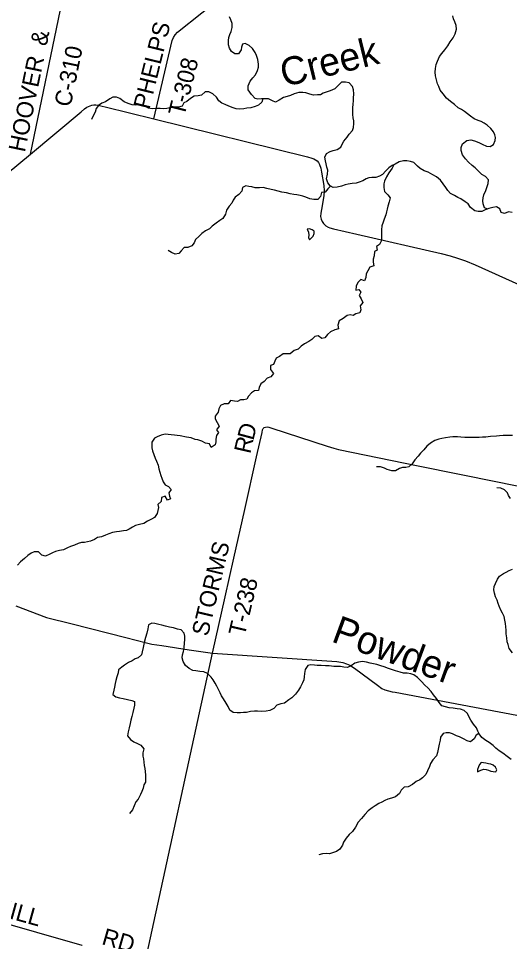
# Model space of a CAD drawing. Extents: x 0 to 34, y 0 to 22.
# Drawn here: x 4.289 to 5.122, y 17.405 to 18.969 of the extents above; entities that cross this region are included whole.
import ezdxf

# ---------------------------------------------------------------- set-up
doc = ezdxf.new("R2010")
doc.units = 0
for name, color, linetype in [('GM_X_County_Road', 7, 'Continuous'), ('GM_X_County_Road_Text', 7, 'Continuous'), ('GM_X_Minor_Lake', 7, 'Continuous'), ('GM_X_Minor_River', 7, 'Continuous'), ('GM_X_Minor_River_Text', 7, 'Continuous'), ('GM_X_State_Route', 7, 'Continuous'), ('GM_X_Township_Road', 7, 'Continuous'), ('GM_X_Township_Road_Text', 7, 'Continuous')]:
    doc.layers.add(name, color=color, linetype=linetype)

msp = doc.modelspace()

# ---------------------------------------------------------------- linework, layer by layer
at = {"layer": 'GM_X_County_Road'}
for points in [[(4.3094, 18.7397), (4.3635, 18.9982), (4.38, 19.0762), (4.4106, 19.2242), (4.44, 19.3619), (4.4954, 19.6213), (4.496, 19.6278)], [(4.2845, 17.9738), (4.3365, 17.9544), (4.3804, 17.9434), (4.4713, 17.9204), (4.5061, 17.9115), (4.5154, 17.9092), (4.5321, 17.9065), (4.5787, 17.8994), (4.6179, 17.894), (4.8287, 17.8794), (4.8392, 17.8777), (4.8453, 17.8759), (4.8506, 17.8734), (4.8585, 17.8684), (4.8976, 17.8393), (4.9051, 17.8341), (4.9104, 17.8318), (4.9166, 17.8299), (4.9228, 17.8284), (4.9275, 17.8274), (5.1759, 17.7808)], [(4.5014, 17.3574), (4.5033, 17.3673), (4.6179, 17.894)]]:
    msp.add_lwpolyline(points, dxfattribs=at)
at = {"layer": 'GM_X_Minor_Lake'}
for points in [[(4.7843, 18.5959), (4.7854, 18.5968), (4.7886, 18.6006), (4.7904, 18.6051), (4.7906, 18.6091), (4.7868, 18.6114), (4.7825, 18.6127), (4.7785, 18.6126)], [(4.7785, 18.6126), (4.7809, 18.6074), (4.7816, 18.6023), (4.7809, 18.5981), (4.7822, 18.5942), (4.7843, 18.5959)], [(5.0986, 17.6992), (5.0978, 17.7007), (5.0939, 17.7042), (5.0901, 17.7059), (5.0857, 17.7063), (5.0814, 17.7073), (5.0774, 17.7081), (5.0733, 17.7086), (5.0704, 17.7053), (5.0687, 17.7009), (5.0675, 17.6966), (5.0673, 17.6926)], [(5.0673, 17.6926), (5.073, 17.6956), (5.0781, 17.6972), (5.0821, 17.6968), (5.0859, 17.6953), (5.0896, 17.6936), (5.094, 17.6932), (5.0985, 17.6929), (5.1002, 17.6963), (5.0986, 17.6992)]]:
    msp.add_lwpolyline(points, dxfattribs=at)
at = {"layer": 'GM_X_Minor_River'}
for points in [[(4.8127, 18.8449), (4.8059, 18.8426), (4.8012, 18.8402), (4.7963, 18.8402), (4.7895, 18.8395), (4.783, 18.8413), (4.7762, 18.8434), (4.7711, 18.8442), (4.7642, 18.8437), (4.7566, 18.8416), (4.7503, 18.839), (4.7445, 18.8371), (4.7382, 18.8353), (4.7312, 18.8308), (4.7249, 18.8274), (4.72, 18.8299), (4.7131, 18.833), (4.7068, 18.8332), (4.701, 18.8331), (4.6951, 18.8327), (4.6902, 18.8335), (4.684, 18.8408), (4.6786, 18.8484), (4.6786, 18.8554), (4.6819, 18.863), (4.6864, 18.8688), (4.6908, 18.8737), (4.6946, 18.8813), (4.6962, 18.8866), (4.6958, 18.8919), (4.6947, 18.8999), (4.6925, 18.9065), (4.6903, 18.9116), (4.686, 18.9185), (4.6803, 18.9238), (4.6737, 18.9271), (4.6688, 18.926), (4.6671, 18.9207), (4.6667, 18.916), (4.6623, 18.9097), (4.6559, 18.9092), (4.6504, 18.9134), (4.6467, 18.9189), (4.645, 18.9246), (4.645, 18.9319), (4.6458, 18.9372), (4.6475, 18.9423), (4.6495, 18.9472), (4.6514, 18.954), (4.6514, 18.9606), (4.6494, 18.9671), (4.6468, 18.972)], [(5.0845, 18.6464), (5.0792, 18.6486), (5.0766, 18.6554), (5.0761, 18.6604), (5.0766, 18.6653), (5.0782, 18.6706), (5.0811, 18.6781), (5.083, 18.6831), (5.0853, 18.6897), (5.0859, 18.6961), (5.081, 18.7015), (5.0744, 18.7051), (5.0697, 18.7103), (5.0633, 18.716), (5.0583, 18.72), (5.0522, 18.7259), (5.0468, 18.7317), (5.0421, 18.7381), (5.0397, 18.7454), (5.0393, 18.7505), (5.042, 18.7571), (5.0492, 18.7627), (5.0557, 18.7636), (5.0623, 18.7619), (5.0693, 18.759), (5.0753, 18.7561), (5.0823, 18.7532), (5.0889, 18.7526), (5.0946, 18.7558), (5.0974, 18.7626), (5.0975, 18.7674), (5.0965, 18.7723), (5.0943, 18.7772), (5.09, 18.7828), (5.0838, 18.7883), (5.0785, 18.7918), (5.0734, 18.7948), (5.0681, 18.7966), (5.0616, 18.7995), (5.0552, 18.8039), (5.0501, 18.8077), (5.045, 18.8119), (5.0399, 18.8151), (5.0344, 18.8182), (5.0281, 18.8236), (5.0217, 18.8289), (5.0145, 18.8343), (5.0091, 18.8415), (5.0042, 18.848), (5.0016, 18.8541), (4.9995, 18.8588), (4.9979, 18.8653), (4.9962, 18.8719), (4.9953, 18.8786), (4.9961, 18.8846), (4.9974, 18.8913), (4.9992, 18.8971), (5.0028, 18.9049), (5.007, 18.91), (5.0121, 18.9164), (5.0169, 18.9232), (5.0211, 18.93), (5.0262, 18.9368), (5.0295, 18.9436), (5.0314, 18.9514), (5.0313, 18.9573), (5.029, 18.9637), (5.0268, 18.969), (5.0253, 18.9738)], [(5.126, 18.6403), (5.1198, 18.6415), (5.1132, 18.6387), (5.1073, 18.6408), (5.1053, 18.6467), (5.0994, 18.6503), (5.0932, 18.6492), (5.0867, 18.6472), (5.0805, 18.645), (5.0744, 18.6423), (5.0682, 18.6422), (5.0625, 18.6436), (5.0554, 18.6491), (5.0516, 18.6554), (5.0466, 18.6588), (5.0388, 18.664), (5.0338, 18.6659), (5.0283, 18.6694), (5.0215, 18.673), (5.0168, 18.678), (5.0134, 18.6827), (5.0093, 18.6894), (5.0046, 18.6951), (4.998, 18.7009), (4.9915, 18.7043), (4.9839, 18.7089), (4.9769, 18.7114), (4.9702, 18.7153), (4.9653, 18.7193), (4.9591, 18.7252), (4.9536, 18.7271), (4.9476, 18.7281), (4.9419, 18.7282), (4.9345, 18.7267), (4.9277, 18.7227), (4.9228, 18.7201), (4.9169, 18.716), (4.9119, 18.7113), (4.906, 18.7047), (4.9013, 18.7022), (4.895, 18.6998), (4.8884, 18.6999), (4.8833, 18.6993), (4.8784, 18.6976), (4.8731, 18.6941), (4.8668, 18.692), (4.8615, 18.6905), (4.8549, 18.6898), (4.8483, 18.6885), (4.8432, 18.6873), (4.8367, 18.685), (4.8294, 18.6835), (4.8226, 18.683), (4.8177, 18.6855), (4.8135, 18.691), (4.8115, 18.6979), (4.8132, 18.7057), (4.8133, 18.7121), (4.8118, 18.7174), (4.8107, 18.7229), (4.8094, 18.7282), (4.8083, 18.7345), (4.8112, 18.7407), (4.8176, 18.7439), (4.8227, 18.7454), (4.8294, 18.7471), (4.8358, 18.7512), (4.8377, 18.7563), (4.8406, 18.7614), (4.8465, 18.7684), (4.8497, 18.7733), (4.8551, 18.7793), (4.857, 18.7846), (4.8576, 18.7913), (4.8574, 18.796), (4.8563, 18.8011), (4.8562, 18.8066), (4.8558, 18.8125), (4.8557, 18.8178), (4.8563, 18.8243), (4.8569, 18.8296), (4.8571, 18.8345), (4.8575, 18.8417), (4.8568, 18.8486), (4.8553, 18.8539), (4.8497, 18.8602), (4.8436, 18.8617), (4.837, 18.8612), (4.8313, 18.8559), (4.8252, 18.8499), (4.8177, 18.8465), (4.8127, 18.8449)], [(4.7036, 18.8331), (4.7017, 18.8274), (4.6962, 18.8227), (4.6901, 18.8202), (4.6829, 18.818), (4.6763, 18.8173), (4.6712, 18.8164), (4.6646, 18.8158), (4.658, 18.8165), (4.6529, 18.8178), (4.6459, 18.8207), (4.6393, 18.8238), (4.634, 18.8257), (4.6288, 18.8297), (4.6246, 18.8358), (4.6186, 18.8417), (4.612, 18.8448), (4.6054, 18.8452), (4.5995, 18.8392), (4.594, 18.8385), (4.5868, 18.838), (4.5808, 18.8338), (4.5743, 18.8286), (4.5696, 18.8267), (4.5667, 18.8205), (4.5607, 18.8192), (4.5531, 18.8192), (4.5465, 18.8181), (4.5408, 18.8168), (4.5342, 18.8163), (4.5291, 18.8167), (4.5227, 18.817), (4.516, 18.8162), (4.5096, 18.8176), (4.5034, 18.8209), (4.4985, 18.8222), (4.4919, 18.8228), (4.4868, 18.8227), (4.4819, 18.8233), (4.4751, 18.8252), (4.4685, 18.8279), (4.461, 18.834), (4.4555, 18.8362), (4.4493, 18.8362), (4.4443, 18.8334), (4.4365, 18.8279), (4.4303, 18.8261), (4.4246, 18.8218), (4.421, 18.8167), (4.4192, 18.8108), (4.4162, 18.8057), (4.4127, 18.7983)], [(4.9255, 18.7216), (4.9227, 18.7158), (4.9168, 18.708), (4.9132, 18.701), (4.9094, 18.6938), (4.9086, 18.6891), (4.9082, 18.6827), (4.9096, 18.6762), (4.9155, 18.6707), (4.9194, 18.6655), (4.9175, 18.6585), (4.9154, 18.6515), (4.914, 18.6464), (4.9132, 18.6415), (4.9121, 18.6364), (4.9092, 18.6294), (4.9076, 18.6244), (4.9051, 18.6178), (4.9044, 18.6114), (4.9045, 18.6042), (4.9043, 18.5994), (4.9048, 18.5932), (4.9012, 18.5864), (4.8959, 18.5832), (4.8972, 18.5767), (4.8924, 18.5747), (4.892, 18.5669), (4.8906, 18.5614), (4.8906, 18.5565), (4.8913, 18.55), (4.8849, 18.5478), (4.8813, 18.5417), (4.8788, 18.5366), (4.878, 18.5302), (4.8757, 18.5247), (4.8693, 18.5272), (4.8645, 18.5221), (4.8618, 18.5157), (4.861, 18.5089), (4.8663, 18.5102), (4.8695, 18.5054), (4.8668, 18.5001), (4.87, 18.4942), (4.8728, 18.4881), (4.8681, 18.4823), (4.8694, 18.4758), (4.868, 18.4707), (4.8612, 18.4687), (4.8563, 18.4662), (4.8512, 18.467), (4.8462, 18.4661), (4.8398, 18.461), (4.8328, 18.4571), (4.8305, 18.4495), (4.8319, 18.4436), (4.8253, 18.4418), (4.8179, 18.4381), (4.813, 18.4339), (4.8084, 18.4283), (4.8033, 18.4271), (4.7971, 18.4315), (4.7914, 18.4303), (4.7867, 18.4254), (4.7813, 18.4218), (4.7739, 18.4182), (4.7681, 18.4143), (4.7631, 18.4092), (4.7565, 18.4066), (4.7495, 18.4008), (4.7434, 18.4012), (4.7379, 18.401), (4.7319, 18.3965), (4.726, 18.3937), (4.7239, 18.3888), (4.7214, 18.3831), (4.7165, 18.3813), (4.7164, 18.3746), (4.7215, 18.3678), (4.7169, 18.3621), (4.7109, 18.3597), (4.7055, 18.354), (4.6997, 18.3503), (4.697, 18.3438), (4.6962, 18.3391), (4.6894, 18.3384), (4.6844, 18.335), (4.6789, 18.3295), (4.6763, 18.3241), (4.6711, 18.323), (4.6653, 18.323), (4.6602, 18.32), (4.6551, 18.3206), (4.6485, 18.322), (4.6446, 18.3165), (4.6377, 18.3163), (4.6316, 18.3134), (4.6287, 18.3079), (4.6276, 18.302), (4.6224, 18.2956), (4.6226, 18.2907), (4.6261, 18.2846)], [(4.818, 18.6853), (4.8135, 18.6806), (4.8089, 18.6751), (4.803, 18.6746), (4.8011, 18.6676), (4.7966, 18.6627), (4.7899, 18.6628), (4.7831, 18.6637), (4.7764, 18.6664), (4.7714, 18.6682), (4.7664, 18.6695), (4.7611, 18.6707), (4.7562, 18.6709), (4.7495, 18.6723), (4.7435, 18.6737), (4.7356, 18.6752), (4.7292, 18.6768), (4.7233, 18.6782), (4.7173, 18.6795), (4.7103, 18.6811), (4.7041, 18.6827), (4.6976, 18.6821), (4.6905, 18.6822), (4.6848, 18.6841), (4.6795, 18.6849), (4.6744, 18.6855), (4.6689, 18.6827), (4.6677, 18.6766), (4.6626, 18.6712), (4.6563, 18.6667), (4.6531, 18.6617), (4.6506, 18.6564), (4.6462, 18.6514), (4.642, 18.6446), (4.6399, 18.6376), (4.6353, 18.6306), (4.6306, 18.6272), (4.6243, 18.6223), (4.6177, 18.6172), (4.6127, 18.6127), (4.6063, 18.6097), (4.6002, 18.6048), (4.5947, 18.5997), (4.589, 18.5946), (4.5871, 18.589), (4.5831, 18.5839), (4.5765, 18.5815), (4.5699, 18.5813), (4.5647, 18.5758), (4.5611, 18.5709), (4.5549, 18.5702), (4.5488, 18.5729), (4.543, 18.5764)], [(4.6261, 18.2846), (4.6293, 18.2785), (4.6251, 18.2723), (4.6283, 18.2675), (4.6249, 18.2626), (4.6237, 18.2565), (4.6235, 18.2518), (4.6225, 18.2469), (4.616, 18.2422), (4.6129, 18.2486), (4.6061, 18.2498), (4.6, 18.2529), (4.5934, 18.2554), (4.5885, 18.256), (4.5819, 18.2587), (4.574, 18.2599), (4.5634, 18.2622), (4.5583, 18.2626), (4.5534, 18.2634), (4.5478, 18.2638), (4.5427, 18.2643), (4.5377, 18.2647), (4.5311, 18.2634), (4.5245, 18.2606), (4.5198, 18.2582), (4.5152, 18.2515), (4.515, 18.2464), (4.5153, 18.2417), (4.5166, 18.2366), (4.5185, 18.2305), (4.5209, 18.2244), (4.5233, 18.2191), (4.5257, 18.2124), (4.5272, 18.2061), (4.5289, 18.2004), (4.5303, 18.1951), (4.5322, 18.1904), (4.5346, 18.1839), (4.5378, 18.1792), (4.5435, 18.1761), (4.548, 18.1709), (4.5442, 18.1653), (4.5453, 18.1601), (4.5466, 18.1554), (4.5416, 18.1533), (4.5377, 18.1596), (4.5314, 18.1574), (4.5308, 18.1506), (4.5253, 18.1459), (4.5266, 18.1409), (4.5253, 18.1356), (4.5241, 18.1307), (4.5197, 18.1235), (4.5146, 18.1207), (4.5076, 18.1172), (4.5017, 18.1134), (4.4945, 18.1117), (4.4877, 18.1099), (4.4822, 18.1071), (4.4769, 18.1039), (4.4721, 18.1018), (4.467, 18.1013), (4.4604, 18.1002), (4.4553, 18.0995), (4.4483, 18.098), (4.4423, 18.0958), (4.4368, 18.0937), (4.4299, 18.0911), (4.4231, 18.0897), (4.418, 18.0865), (4.4112, 18.0835), (4.4061, 18.0824), (4.401, 18.0815), (4.3959, 18.0813), (4.3906, 18.0798), (4.3843, 18.077), (4.3775, 18.0746), (4.3722, 18.072), (4.3657, 18.069), (4.3586, 18.0677), (4.3519, 18.0658), (4.347, 18.0636), (4.3423, 18.0616), (4.3351, 18.058), (4.3286, 18.0596), (4.323, 18.0653), (4.316, 18.0655), (4.3109, 18.0633), (4.305, 18.0595), (4.2991, 18.0541), (4.2927, 18.0484), (4.2873, 18.0428)], [(5.1264, 18.2624), (5.1213, 18.2624), (5.1162, 18.2624), (5.1106, 18.2627), (5.1043, 18.2619), (5.0992, 18.2616), (5.0894, 18.2609), (5.0815, 18.26), (5.0756, 18.2597), (5.0701, 18.2593), (5.0641, 18.2592), (5.058, 18.2592), (5.0523, 18.2594), (5.0459, 18.2595), (5.0391, 18.2599), (5.0335, 18.2605), (5.0257, 18.2602), (5.0202, 18.2598), (5.013, 18.2589), (5.0066, 18.2576), (5.0017, 18.2562), (4.9949, 18.2539), (4.9878, 18.2494), (4.9816, 18.2447), (4.9764, 18.2383), (4.9709, 18.2325), (4.9664, 18.2276), (4.961, 18.2215), (4.9565, 18.2149), (4.9509, 18.2098), (4.9458, 18.2083), (4.9402, 18.2082), (4.9352, 18.2069), (4.9284, 18.203), (4.922, 18.2026), (4.9144, 18.2053), (4.9095, 18.2071), (4.9031, 18.2096), (4.8963, 18.2094)], [(5.123, 18.156), (5.12, 18.1608), (5.1181, 18.1655), (5.1129, 18.1707), (5.1066, 18.1732), (5.1002, 18.1738)], [(5.0958, 17.9954), (5.0947, 18.0009), (5.0956, 18.0066), (5.0976, 18.0121), (5.1014, 18.0192), (5.1044, 18.0242), (5.1111, 18.029), (5.1158, 18.0313), (5.1207, 18.0337), (5.1264, 18.036)], [(5.1267, 17.8945), (5.1211, 17.9017), (5.1191, 17.9082), (5.1178, 17.913), (5.1171, 17.92), (5.116, 17.9268), (5.1156, 17.9325), (5.1155, 17.9382), (5.1146, 17.9443), (5.1134, 17.9496), (5.1122, 17.9557), (5.1095, 17.9614), (5.1066, 17.9667), (5.1041, 17.9732), (5.1023, 17.9781), (5.1004, 17.9834), (5.0976, 17.9895), (5.0958, 17.9954)], [(4.8723, 17.8795), (4.8654, 17.8788), (4.8596, 17.8769), (4.8533, 17.8722), (4.8471, 17.8696), (4.8406, 17.8702), (4.835, 17.8714), (4.8238, 17.8714), (4.8157, 17.8721), (4.8097, 17.8725), (4.8025, 17.8727), (4.7957, 17.873), (4.7908, 17.8736), (4.7845, 17.8738), (4.7794, 17.8727), (4.7754, 17.8661), (4.7739, 17.8591), (4.7736, 17.8536), (4.7729, 17.8486), (4.7707, 17.8437), (4.7675, 17.8369), (4.7637, 17.8311), (4.7589, 17.8245), (4.7526, 17.8182), (4.7473, 17.8149), (4.7403, 17.809), (4.7341, 17.8079), (4.727, 17.8055), (4.7219, 17.8001), (4.7153, 17.7965), (4.709, 17.7954), (4.7011, 17.7951), (4.6943, 17.7957), (4.689, 17.7957), (4.6822, 17.795), (4.6756, 17.7935), (4.6707, 17.7932), (4.6657, 17.7925), (4.6597, 17.7927), (4.6531, 17.7935), (4.6476, 17.7969), (4.6444, 17.8034), (4.6413, 17.8089), (4.6368, 17.8162), (4.6334, 17.8213), (4.631, 17.8266), (4.628, 17.8321), (4.6252, 17.8377), (4.6228, 17.8428), (4.619, 17.8483), (4.6156, 17.8531), (4.6098, 17.8594), (4.6034, 17.8619), (4.5968, 17.8627), (4.5896, 17.8639), (4.5845, 17.8643), (4.5783, 17.8677), (4.5721, 17.8727), (4.5684, 17.8796), (4.5669, 17.886), (4.5671, 17.8908), (4.569, 17.8966), (4.5702, 17.9034), (4.5708, 17.9108), (4.5714, 17.9167), (4.5711, 17.9228), (4.5702, 17.9275), (4.5651, 17.9331), (4.5587, 17.9346), (4.5517, 17.9366), (4.5449, 17.9379), (4.5383, 17.9395), (4.5321, 17.941), (4.5271, 17.9424), (4.5202, 17.944), (4.5151, 17.9446), (4.5096, 17.9416), (4.5084, 17.9349), (4.5066, 17.9277), (4.5045, 17.9206), (4.503, 17.9143), (4.5018, 17.9088), (4.5006, 17.9035), (4.4987, 17.8961), (4.4975, 17.8908), (4.4918, 17.8858), (4.4869, 17.8841), (4.482, 17.8809), (4.4754, 17.8777), (4.4689, 17.8734), (4.4642, 17.8702), (4.4587, 17.8653), (4.4579, 17.8604), (4.4561, 17.8538), (4.4542, 17.8473), (4.4528, 17.8422), (4.4519, 17.8361), (4.4507, 17.8308), (4.449, 17.8238), (4.454, 17.8196), (4.4603, 17.8181)], [(5.1243, 17.7136), (5.1176, 17.7186), (5.1102, 17.7243), (5.1042, 17.7285), (5.0984, 17.7326), (5.0937, 17.7375), (5.0873, 17.7421), (5.0814, 17.7456), (5.0747, 17.7509), (5.0698, 17.757), (5.0677, 17.7618), (5.0653, 17.7671), (5.0606, 17.7736), (5.0561, 17.7801), (5.0524, 17.7863), (5.0503, 17.7917), (5.0445, 17.7964), (5.0387, 17.7987), (5.0328, 17.7995), (5.0258, 17.8005), (5.0194, 17.8013), (5.013, 17.8029), (5.0069, 17.8046), (5.0024, 17.8102), (4.9976, 17.8168), (4.9929, 17.8231), (4.9888, 17.829), (4.9833, 17.8349), (4.9782, 17.8395), (4.9724, 17.8458), (4.9656, 17.8523), (4.9594, 17.8569), (4.954, 17.8588), (4.9479, 17.86), (4.9417, 17.8601), (4.936, 17.8618), (4.9283, 17.8637), (4.9215, 17.8663), (4.9162, 17.8678), (4.9092, 17.8705), (4.9036, 17.8722), (4.8964, 17.8744), (4.8908, 17.8756), (4.8851, 17.8769), (4.8792, 17.8785), (4.8723, 17.8795)], [(4.4603, 17.8181), (4.4665, 17.8171), (4.474, 17.8155), (4.4812, 17.8134), (4.4861, 17.812), (4.4861, 17.8054), (4.4847, 17.8003), (4.4828, 17.7935), (4.4812, 17.7867), (4.4799, 17.7802), (4.4785, 17.7744), (4.4766, 17.767), (4.4749, 17.7603), (4.4741, 17.7535), (4.4789, 17.7474), (4.4848, 17.7434), (4.4908, 17.7405), (4.4966, 17.7376), (4.5015, 17.7319), (4.5002, 17.7251), (4.4997, 17.7194), (4.5009, 17.7145), (4.5018, 17.7092), (4.5023, 17.7035), (4.5034, 17.6985), (4.5039, 17.6932), (4.5043, 17.6872), (4.5044, 17.6818), (4.5042, 17.6754), (4.5019, 17.6705), (4.5004, 17.6648), (4.4981, 17.6593), (4.4961, 17.654), (4.4921, 17.6465), (4.4881, 17.6416), (4.4853, 17.6348), (4.4822, 17.6283), (4.4772, 17.6219)], [(5.0696, 17.7576), (5.0649, 17.7546), (5.0618, 17.7485), (5.0555, 17.7435), (5.0497, 17.7454), (5.0433, 17.7487), (5.0369, 17.7517), (5.0316, 17.7535), (5.0248, 17.7571), (5.0197, 17.7587), (5.0144, 17.7589), (5.0093, 17.7576), (5.0047, 17.7514), (5.0038, 17.7463), (5.0024, 17.7393), (5.0006, 17.7309), (4.9997, 17.7254), (4.9976, 17.7199), (4.9917, 17.7132), (4.9877, 17.7069), (4.9857, 17.7016), (4.9823, 17.6941), (4.9798, 17.6884), (4.9741, 17.6827), (4.9693, 17.6792), (4.9633, 17.6764), (4.957, 17.6711), (4.9496, 17.6675), (4.943, 17.6665), (4.9379, 17.6614), (4.9352, 17.6561), (4.9285, 17.6504), (4.9215, 17.6482), (4.9151, 17.6463), (4.9102, 17.6441), (4.9051, 17.6415), (4.8999, 17.6391), (4.8939, 17.6349), (4.8887, 17.6317), (4.8819, 17.6263), (4.8764, 17.6206), (4.8709, 17.6133), (4.8652, 17.6076), (4.8602, 17.5991), (4.8554, 17.5914), (4.8495, 17.5865), (4.8446, 17.5804), (4.8402, 17.5735), (4.8383, 17.5685), (4.8341, 17.5617), (4.8282, 17.5578), (4.8212, 17.5552), (4.8161, 17.5537), (4.8108, 17.5545), (4.8046, 17.5536), (4.7983, 17.5521)]]:
    msp.add_lwpolyline(points, dxfattribs=at)
at = {"layer": 'GM_X_State_Route'}
msp.add_lwpolyline([(4.1938, 18.6441), (4.3094, 18.7397), (4.3952, 18.8112), (4.4012, 18.8161), (4.4051, 18.8188), (4.4078, 18.8203), (4.4106, 18.8214), (4.4136, 18.8223), (4.417, 18.8228), (4.4204, 18.8228), (4.4241, 18.8223), (4.4312, 18.8208), (4.4359, 18.8197), (4.5187, 18.7991), (4.7791, 18.7349), (4.7864, 18.7329), (4.79, 18.7314), (4.7926, 18.7299), (4.7952, 18.7281), (4.7979, 18.7251), (4.7997, 18.722), (4.8016, 18.7159), (4.803, 18.709), (4.8066, 18.6866), (4.8074, 18.6775), (4.8067, 18.669), (4.8028, 18.6457), (4.8018, 18.6395), (4.8014, 18.6338), (4.8024, 18.6292), (4.804, 18.6252), (4.8061, 18.622), (4.8103, 18.618), (4.8139, 18.6159), (4.8169, 18.6147), (4.8231, 18.613), (4.8626, 18.6039), (5.0055, 18.5709), (5.0207, 18.5671), (5.0336, 18.5633), (5.0469, 18.5585), (5.0632, 18.5517), (5.2003, 18.4901)], dxfattribs=at)
at = {"layer": 'GM_X_Township_Road'}
for points in [[(4.5187, 18.7991), (4.5499, 18.9321), (4.5517, 18.9372), (4.5546, 18.9419), (4.5585, 18.9461), (4.6414, 19.0121), (4.6465, 19.0155), (4.6549, 19.0178), (4.6636, 19.0178), (4.7005, 19.016), (4.7147, 19.0159), (4.7619, 19.0184), (4.7668, 19.0192), (4.7707, 19.0222), (4.7727, 19.0268), (4.7744, 19.0345), (4.8328, 19.3197), (4.8374, 19.3387)], [(4.6179, 17.894), (4.6395, 17.9893), (4.6542, 18.0547), (4.6728, 18.1375), (4.6924, 18.2264), (4.7021, 18.268), (4.7028, 18.272), (4.704, 18.2746), (4.7059, 18.276), (4.708, 18.2769), (4.711, 18.2773), (4.7136, 18.2769), (4.7188, 18.2751), (4.8124, 18.2448), (4.8238, 18.2414), (4.8319, 18.2392), (4.9665, 18.2115), (5.1042, 18.1833), (5.1893, 18.1658)], [(4.1657, 17.4652), (4.3967, 17.3988), (4.3972, 17.3986)]]:
    msp.add_lwpolyline(points, dxfattribs=at)

# ---------------------------------------------------------------- texts
at = {"layer": 'GM_X_County_Road_Text'}
for s, height, rotation, p in [('&', 0.0284, 78.5174, (4.3368, 18.9216)), ('C-310', 0.02841, 78.3665, (4.3774, 18.8182)), ('HOOVER', 0.02841, 78.3664, (4.2998, 18.7416))]:
    msp.add_text(s, height=height, rotation=rotation, dxfattribs=at).set_placement(p)
at = {"layer": 'GM_X_Minor_River_Text'}
for s, rotation, p in [('Creek', 13.7959, (4.7393, 18.853)), ('Powder', 339.8856, (4.8177, 17.914))]:
    msp.add_text(s, height=0.04735, rotation=rotation, dxfattribs=at).set_placement(p)
at = {"layer": 'GM_X_Township_Road_Text'}
for s, height, rotation, p in [('PHELPS', 0.02841, 76.1488, (4.5111, 18.8141)), ('T-308', 0.02841, 75.8277, (4.5702, 18.8023)), ('D', 0.0284, 75.0104, (4.6871, 18.2531)), ('R', 0.0284, 77.061, (4.6819, 18.2306)), ('STORMS', 0.02841, 76.7103, (4.6102, 17.9211)), ('T-238', 0.02841, 76.7112, (4.6725, 17.9214)), ('CAHILL', 0.02841, 344.4656, (4.195, 17.466)), ('RD', 0.02841, 344.0556, (4.4288, 17.4009))]:
    msp.add_text(s, height=height, rotation=rotation, dxfattribs=at).set_placement(p)

doc.saveas('drawing.dxf')
